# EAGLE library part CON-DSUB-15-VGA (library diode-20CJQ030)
NORCOMP's High Density 90° PC Mount D-Sub Connector 181 Series: SPECIFICATIONS: Contact Rating: 5 Amps Dielectric Strength: 1000V AC RMS Insulation Resistance: 1000 meg ohms Contact Material: Phosphor Bronze Contact Finish: Gold flash over Nickel Operating Temperature: -55°C to 150°C Shell Material: Steel, Tin Plated Insulations Material: Glass-Filled Polyester (UL94V-0) Gender: Receptacle (female) Please send any comments to: messi@users.sourceforge.net
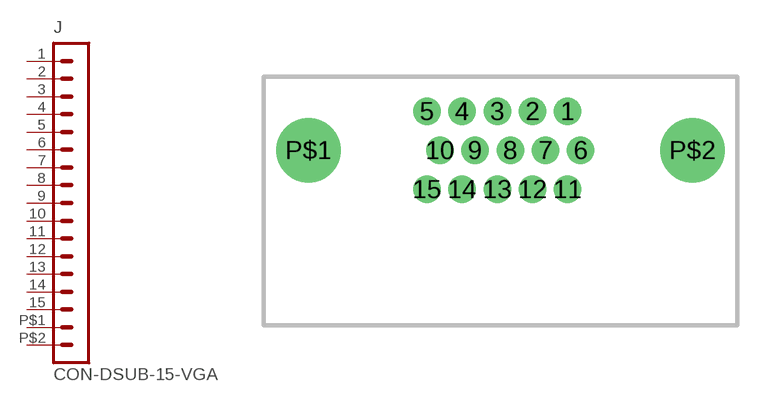
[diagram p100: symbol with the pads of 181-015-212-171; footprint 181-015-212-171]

Designator prefix J

## CON-DSUB-15-VGA  [181-015-212-171]
1  1  pas
2  2  pas
3  3  pas
4  4  pas
5  5  pas
6  6  pas
7  7  pas
8  8  pas
9  9  pas
10  10  pas
11  11  pas
12  12  pas
13  13  pas
14  14  pas
15  15  pas
P$1  16  pas
P$2  17  pas

## Footprint 181-015-212-171 (pad centres in mm)
drill 1.194 round: 1 4.371,2.541; 2 2.08,2.541; 3 -0.211,2.541; 4 -2.502,2.541; 5 -4.793,2.541; 6 5.217,0; 7 2.926,0; 8 0.635,0; 9 -1.656,0; 10 -3.947,0; 11 4.371,-2.541; 12 2.08,-2.541; 13 -0.211,-2.541; 14 -2.502,-2.541; 15 -4.793,-2.541
drill 3.2 round: P$1 -12.502,0; P$2 12.502,0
